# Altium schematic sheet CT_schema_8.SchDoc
size 278 x 170 mm
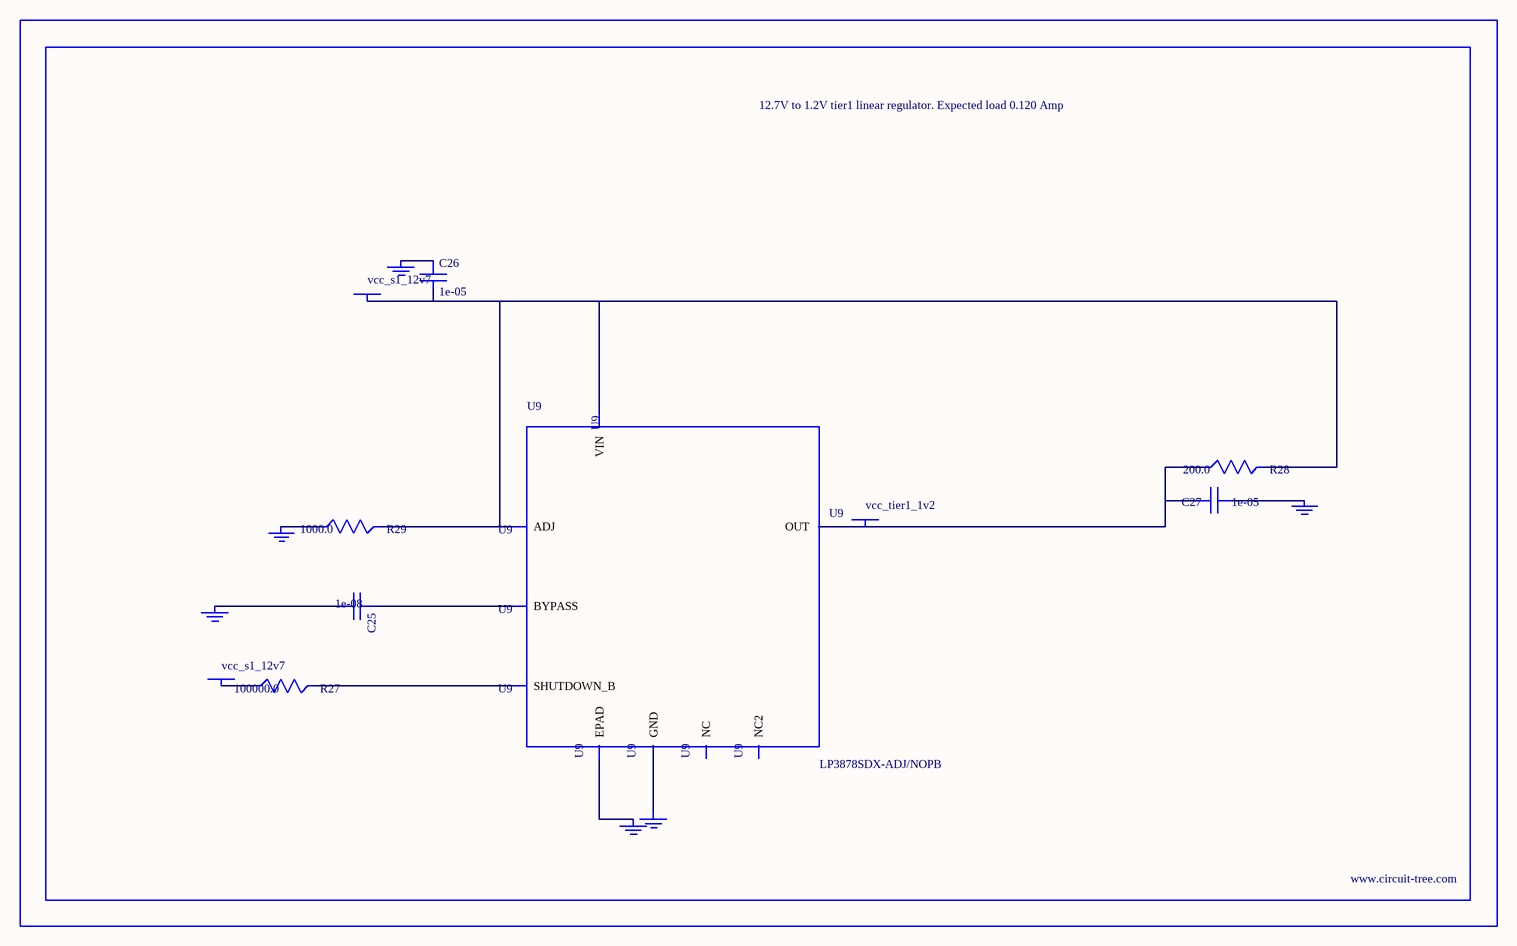
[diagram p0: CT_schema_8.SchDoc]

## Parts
BORDER7  (no value)
C25  1e-08  [C0402]
C26  1e-05  [C1210]
C27  1e-05  [C0805]
GND_INSTANCE_7_0  (no value)
GND_INSTANCE_7_1  (no value)
GND_INSTANCE_7_2  (no value)
GND_INSTANCE_7_3  (no value)
GND_INSTANCE_7_4  (no value)
GND_INSTANCE_7_5  (no value)
POWER_INSTANCE_7_0  vcc_s1_12v7
POWER_INSTANCE_7_1  vcc_s1_12v7
POWER_INSTANCE_7_2  vcc_tier1_1v2
R27  100000.0  [R0603]
R28  200.0  [R0603]
R29  1000.0  [R0603]
U9  LP3878SDX-ADJ/NOPB  [WSON-8]

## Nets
NetC25_1: C25.1 U9.1(BYPASS)
NetC25_2: C25.2 GND_INSTANCE_7_0.0(GND)
NetC26_1: C26.1 GND_INSTANCE_7_1.0(GND)
NetC26_2: C26.2 POWER_INSTANCE_7_0.0(PWR) R28.2 R29.2 U9.4(VIN) U9.6(ADJ)
NetC27_1: C27.1 GND_INSTANCE_7_2.0(GND)
NetC27_2: C27.2 POWER_INSTANCE_7_2.0(PWR) R28.1 U9.5(OUT)
NetGND_INSTANCE_7_3_0: GND_INSTANCE_7_3.0(GND) R29.1
NetGND_INSTANCE_7_4_0: GND_INSTANCE_7_4.0(GND) U9.PAD(EPAD)
NetGND_INSTANCE_7_5_0: GND_INSTANCE_7_5.0(GND) U9.3(GND)
NetPOWER_INSTANCE_7_1_0: POWER_INSTANCE_7_1.0(PWR) R27.1
NetR27_2: R27.2 U9.8(SHUTDOWN_B)

Not connected (* = marked no-connect by the designer): U9 2(NC) 7(NC2)

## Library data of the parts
BORDER7 = BORDER_PAGE7
C25 = C0402C103K3RAC
C26 = C1210C106K5PACTU
C27 = GRM219R60J106ME19D
GND_INSTANCE_7_0-GND_INSTANCE_7_5 = GND
POWER_INSTANCE_7_0-POWER_INSTANCE_7_2 = PWR
R27 = RC0603JR-07100KL
R28 = RC0603JR-07200RL
R29 = RC0603JR-071KL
